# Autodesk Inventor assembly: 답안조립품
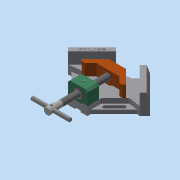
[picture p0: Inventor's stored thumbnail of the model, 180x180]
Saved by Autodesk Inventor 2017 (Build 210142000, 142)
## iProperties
Part Number: 답안조립품
Material: 일반
Document SubType Name: Assembly
Designer: 222
Author: 222
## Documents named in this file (11)
- C:\Users\222\Desktop\700506V1050\답안조립품.iam
- C:\Users\222\Desktop\700506V1050\리드스크류.ipt
- C:\Users\222\Desktop\700506V1050\멈춤나사 M4x5.ipt
- C:\Users\222\Desktop\700506V1050\멈춤나사 M4x10.ipt
- C:\Users\222\Desktop\700506V1050\본체.ipt
- C:\Users\222\Desktop\700506V1050\볼트 M4x16.ipt
- C:\Users\222\Desktop\700506V1050\부시.ipt
- C:\Users\222\Desktop\700506V1050\서포트.ipt
- C:\Users\222\Desktop\700506V1050\조.ipt
- C:\Users\222\Desktop\700506V1050\평행 핀 2.5x24.ipt
- C:\Users\222\Desktop\700506V1050\핸들.ipt
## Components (1 placed, 1 different names)
1. 핸들:1
